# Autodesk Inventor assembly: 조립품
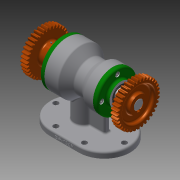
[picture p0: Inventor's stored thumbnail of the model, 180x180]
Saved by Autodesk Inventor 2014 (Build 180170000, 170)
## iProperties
Created: 2020-01
Part Number: 조립품
Document SubType Name: Assembly
Designer: kh
Author: kh
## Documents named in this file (13)
- C:\Users\kh\Desktop\700104V1033\조립품.iam
- C:\Users\kh\Desktop\700104V1033\본체.ipt
- C:\Users\kh\Desktop\700104V1033\Ű 5 x 5 x 18.ipt
- C:\Users\kh\Desktop\700104V1033\뒤커버.ipt
- C:\Users\kh\Desktop\700104V1033\멈춤나사 M3.ipt
- C:\Users\kh\Desktop\700104V1033\베어링 6203.ipt
- C:\Users\kh\Desktop\700104V1033\베어링 6205.ipt
- C:\Users\kh\Desktop\700104V1033\볼트 M4.ipt
- C:\Users\kh\Desktop\700104V1033\스퍼기어.ipt
- C:\Users\kh\Desktop\700104V1033\앞커버.ipt
- C:\Users\kh\Desktop\700104V1033\오일 실 17 30 8.ipt
- C:\Users\kh\Desktop\700104V1033\오일 실 25 38 8.ipt
- C:\Users\kh\Desktop\700104V1033\축.ipt
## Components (2 placed, 1 different names)
1. Ű 5 x 5 x 18:1 — Mate:18, Mate:19, Mate:20, Mate:26, Mate:28, Angle:1
2. Ű 5 x 5 x 18:2 — Mate:15, Mate:16, Mate:17, Mate:22, Mate:24
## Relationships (11: Mate 10, Angle 1)
- Mate:15: Ű 5 x 5 x 18:2
- Mate:16: Ű 5 x 5 x 18:2
- Mate:17: Ű 5 x 5 x 18:2
- Mate:18: Ű 5 x 5 x 18:1
- Mate:19: Ű 5 x 5 x 18:1
- Mate:20: Ű 5 x 5 x 18:1
- Mate:22: Ű 5 x 5 x 18:2
- Mate:24: Ű 5 x 5 x 18:2
- Mate:26: Ű 5 x 5 x 18:1
- Mate:28: Ű 5 x 5 x 18:1
- Angle:1: Ű 5 x 5 x 18:1
